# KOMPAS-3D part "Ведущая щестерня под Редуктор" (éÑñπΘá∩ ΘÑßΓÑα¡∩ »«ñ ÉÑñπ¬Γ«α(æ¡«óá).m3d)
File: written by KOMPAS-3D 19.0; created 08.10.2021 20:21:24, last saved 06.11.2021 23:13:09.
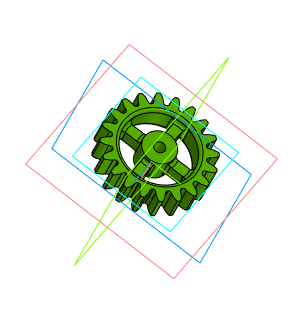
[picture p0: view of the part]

Document properties: Автор: Дымок(R); Организация: PDA-NN.3dn.ru; Полное имя файла: D:\3D_print\3D проекты Компас 3D\Редуктор (Снова)\Ведущая щестерня под Редуктор(Снова).m3d

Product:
- Part/product: Ведущая щестерня под Редуктор
    Материал: АБС 0603Т ТУ 2214-019-002 03521-96 (density 0 kg/m3)

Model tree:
1. ЛСК (Шестерня цилиндрическая с внешними зубьями):1  (with: Шестерня цилиндрическая с внешними зубьями:1, Плоскость XY, Плоскость ZX, Плоскость ZY, Ось X, Ось Y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)  (labels: &Фаска (Шестерня цилиндрическая с внешними зубьями):1)
     Ось X. X = 1; Ось Y. Y = 1; Ось Z. Z = 1; Угол 1 = 360
2. Эскиз для винтовой линии (Шестерня цилиндрическая с внешними зубьями):1  (with: Винтовая линия (Шестерня цилиндрическая с внешними зубьями):1, Шестерня цилиндрическая с внешними зубьями:1, Впадина прямая (Шестерня цилиндрическая с внешними зубьями):1, Впадина косая (Шестерня цилиндрическая с внешними зубьями):1, Массив впадин (Шестерня цилиндрическая с внешними зубьями):1)  (2 pattern instances)
     Число витков = 0.00742627; Смещение 2 = 8
3. Впадина прямая (Шестерня цилиндрическая с внешними зубьями):1  (with: Массив впадин (Шестерня цилиндрическая с внешними зубьями):1, Шестерня цилиндрическая с внешними зубьями:1)  (20 pattern instances)
     N 1 = 1; Шаг 1 = 1; Номер 1 = 1
4. Впадина косая (Шестерня цилиндрическая с внешними зубьями):1  (with: Винтовая линия (Шестерня цилиндрическая с внешними зубьями):1)
     N 1 = 1; Шаг 1 = 1; Номер 1 = 1
5. Шестерня цилиндрическая с внешними зубьями:1
6. Эскиз:5  (with: Цилиндр (Шестерня цилиндрическая с внешними зубьями):1)
7. Элемент выдавливания:3
8. Средняя плоскость:1  (with: Цилиндр (Шестерня цилиндрическая с внешними зубьями):1)
9. Эскиз:7  (with: Цилиндр (Шестерня цилиндрическая с внешними зубьями):1)
10. Элемент выдавливания:5
11. Эскиз:8  (with: Цилиндр (Шестерня цилиндрическая с внешними зубьями):1, Элемент выдавливания:5)
12. Элемент выдавливания:6
     Расстояние 2 = 2
13. Эскиз:9  (with: Цилиндр (Шестерня цилиндрическая с внешними зубьями):1, Элемент выдавливания:5)
14. Элемент выдавливания:7
     Расстояние 2 = 2
15. Скругление:2  (with: Элемент выдавливания:6)
     Радиус = 1
16. Скругление:3  (with: Элемент выдавливания:7)
     Радиус = 1
17. Скругление:4  (with: Элемент выдавливания:5)
     Радиус = 1
18. Скругление:5  (with: Элемент выдавливания:5)
     Радиус = 1
19. Скругление:6  (with: Элемент выдавливания:5)  (labels: АБС 0603Т ТУ 2214-019-002 03521-96)
     Радиус = 1

Expressions: (VGExtS_1_z*VGExtS_1_M)/COSD(VGExtS_1_Beta); 360/VGExtS_1_z
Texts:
  SHAFT3D
  Количество отображаемых зубьев
  Угол наклона линии зубьев
  Шаг по кольцевому направлению
  (VGExtS_1_Beta>0)?(M_PI*VGExtS_1_z*VGExtS_1_M/SIND(VGExtS_1_Beta)):1000
  (VGExtS_1_Da<=0||VGExtS_1_Da>5e+7)?25:VGExtS_1_Da
  (VGExtS_1_H<=0||VGExtS_1_H>5e+7)?25:VGExtS_1_H
  VGExtS_1_zz<VGExtS_1_z?(VGExtS_1_zz+1):VGExtS_1_z
  (VGExtS_1_zz<=0||VGExtS_1==1)||(VGExtS_1_Beta>0)?1:0
  (VGExtS_1_zz<=0||VGExtS_1==1)||(VGExtS_1_Beta<=0)?1:0
  (VGExtS_1==1)||(VGExtS_1_Beta<=0)?1:0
